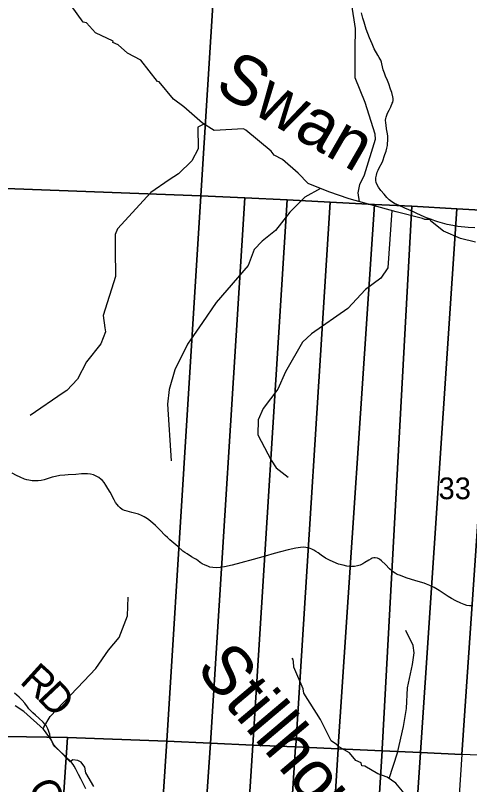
# Model space of a CAD drawing. Extents: x 0 to 34, y 0 to 22.
# Drawn here: x 6.766 to 7.641, y 15.074 to 16.555 of the extents above; entities that cross this region are included whole.
import ezdxf

# ---------------------------------------------------------------- set-up
doc = ezdxf.new("R2010")
doc.units = 0
for name, color, linetype in [('Default', 7, 'Continuous'), ('GM_X_County_Road', 7, 'Continuous'), ('GM_X_County_Road_Text', 7, 'Continuous'), ('GM_X_Minor_River', 7, 'Continuous'), ('GM_X_Minor_River_Text', 7, 'Continuous'), ('GM_X_Section', 7, 'Continuous'), ('GM_X_Section_Text', 7, 'Continuous'), ('GM_X_Township_Road', 7, 'Continuous')]:
    doc.layers.add(name, color=color, linetype=linetype)

msp = doc.modelspace()

# ---------------------------------------------------------------- linework, layer by layer
at = {"layer": 'Default'}
msp.add_lwpolyline([(7.6316, 14.1), (7.6406, 14.1), (7.7063, 15.1284), (7.6256, 15.132), (7.558, 14.1033)], close=True, dxfattribs=at)
at = {"layer": 'GM_X_County_Road'}
for points in [[(7.6442, 15.4183), (7.6401, 15.4183), (7.6354, 15.419), (7.6299, 15.4209), (7.6235, 15.4235), (7.6141, 15.4277), (7.6054, 15.4325), (7.599, 15.4363), (7.5818, 15.4477), (7.572, 15.4532), (7.5637, 15.4575), (7.5573, 15.46), (7.5528, 15.4616), (7.5461, 15.4637), (7.5354, 15.467), (7.5288, 15.4689), (7.5187, 15.4722), (7.5073, 15.4763), (7.5013, 15.4787), (7.497, 15.4811), (7.494, 15.483), (7.4908, 15.4855), (7.4862, 15.4896), (7.4784, 15.4978), (7.4711, 15.5047), (7.4669, 15.5078), (7.463, 15.5098), (7.4588, 15.5104), (7.4559, 15.5103), (7.4532, 15.5097), (7.4511, 15.5089), (7.4463, 15.5063), (7.439, 15.5016), (7.4347, 15.4991), (7.4297, 15.4966), (7.4246, 15.4949), (7.4188, 15.4937), (7.4143, 15.4938), (7.4095, 15.494), (7.4044, 15.4946), (7.3971, 15.4963), (7.3881, 15.4987), (7.3776, 15.5026), (7.3706, 15.5058), (7.3632, 15.5102), (7.3545, 15.5159), (7.3486, 15.5203), (7.3441, 15.5231), (7.3406, 15.5254), (7.337, 15.5273), (7.3337, 15.5287), (7.3293, 15.53), (7.3254, 15.5308), (7.3204, 15.5311), (7.315, 15.5307), (7.3058, 15.5291), (7.2914, 15.5259), (7.2761, 15.5221), (7.2641, 15.5191), (7.2468, 15.5141), (7.224, 15.5077), (7.1999, 15.5012), (7.1832, 15.4966), (7.1687, 15.4934), (7.1601, 15.4921), (7.154, 15.4916), (7.146, 15.492), (7.1404, 15.4929), (7.1362, 15.4943), (7.1311, 15.4964), (7.1256, 15.4993), (7.1219, 15.5016), (7.1173, 15.5052), (7.1133, 15.508), (7.111, 15.5094), (7.1051, 15.5127), (7.0967, 15.5181), (7.0922, 15.5208), (7.0882, 15.5236), (7.0783, 15.5325), (7.0634, 15.5453), (7.0585, 15.5498), (7.0545, 15.5536), (7.0442, 15.5644), (7.0355, 15.573), (7.026, 15.5813), (7.02, 15.5858), (7.0139, 15.5895), (7.0086, 15.5922), (7.0031, 15.5946), (6.9976, 15.5963), (6.9902, 15.5981), (6.9807, 15.6004), (6.9759, 15.6019), (6.9717, 15.604), (6.9678, 15.6068), (6.9643, 15.6099), (6.9616, 15.6131), (6.9587, 15.6171), (6.9559, 15.6222), (6.948, 15.6372), (6.9439, 15.6443), (6.9402, 15.6508), (6.9367, 15.6558), (6.9336, 15.6595), (6.9311, 15.6618), (6.9264, 15.6652), (6.9215, 15.6679), (6.916, 15.6703), (6.9101, 15.6717), (6.9046, 15.6725), (6.8984, 15.6726), (6.8929, 15.6721), (6.8822, 15.6712), (6.8676, 15.6702), (6.8607, 15.6698), (6.8514, 15.6689), (6.8429, 15.6674), (6.8364, 15.6657), (6.8209, 15.6608), (6.8155, 15.6595), (6.8093, 15.6587), (6.8042, 15.6586), (6.798, 15.6591), (6.7918, 15.6601), (6.788, 15.6609), (6.7834, 15.6622), (6.7752, 15.6657), (6.7676, 15.6692), (6.7592, 15.6739)], [(6.9012, 15.0659), (6.8919, 15.0851), (6.8875, 15.0934), (6.882, 15.1037), (6.8789, 15.1093), (6.8767, 15.1126), (6.8723, 15.1181), (6.8624, 15.1279), (6.8483, 15.1413), (6.8435, 15.146), (6.8397, 15.1507), (6.8372, 15.1548), (6.8357, 15.1579), (6.8343, 15.1613), (6.833, 15.1654), (6.8318, 15.1707), (6.8309, 15.1743), (6.8295, 15.1782), (6.8285, 15.1813), (6.8271, 15.1838), (6.8247, 15.1876), (6.8226, 15.1901), (6.8191, 15.1941), (6.811, 15.2015), (6.8044, 15.2074), (6.7995, 15.2121), (6.7955, 15.2157), (6.7919, 15.2196), (6.7888, 15.2235), (6.7836, 15.2305), (6.7786, 15.2364), (6.7729, 15.242), (6.7639, 15.2497)]]:
    msp.add_lwpolyline(points, dxfattribs=at)
at = {"layer": 'GM_X_Minor_River'}
for points in [[(7.1484, 16.3335), (7.1264, 16.3481), (7.09, 16.3792), (7.07, 16.394), (7.0424, 16.4277), (7.0393, 16.4281), (7.0076, 16.4691), (6.9815, 16.4827), (6.9637, 16.4986), (6.9535, 16.5032), (6.9542, 16.5058), (6.9198, 16.5221), (6.9024, 16.5414), (6.896, 16.5426), (6.8729, 16.5744), (6.8555, 16.5884), (6.8433, 16.5816), (6.8522, 16.5865)], [(7.4284, 16.1962), (7.426, 16.2136), (7.4292, 16.2298), (7.438, 16.2481), (7.4594, 16.3173), (7.4589, 16.3264), (7.4393, 16.3878), (7.4199, 16.4351), (7.4204, 16.4898), (7.4205, 16.5301), (7.414, 16.5758)], [(7.1302, 16.3465), (7.1169, 16.34), (7.1179, 16.2986), (7.1055, 16.2751), (7.0801, 16.2501), (7.0616, 16.2385), (7.0269, 16.2142), (6.9624, 16.1445), (6.9579, 16.1333), (6.9578, 16.1048), (6.9585, 16.0524), (6.935, 15.9772), (6.9381, 15.9535), (6.9394, 15.9459), (6.9304, 15.923), (6.9025, 15.8882), (6.8852, 15.8546), (6.8649, 15.8332), (6.8575, 15.8282), (6.7942, 15.785)], [(7.2052, 16.3367), (7.1484, 16.3335)], [(7.652, 16.1186), (7.6233, 16.1258), (7.5904, 16.1398), (7.565, 16.1598), (7.5658, 16.1621), (7.5545, 16.1625), (7.5499, 16.1644), (7.4989, 16.1772), (7.4089, 16.2021), (7.3696, 16.2153), (7.3298, 16.2319), (7.3105, 16.2516), (7.2799, 16.2778), (7.264, 16.2861), (7.2583, 16.2937), (7.2095, 16.3342), (7.2052, 16.3367)], [(7.3532, 16.2221), (7.3233, 16.2055), (7.2945, 16.1764), (7.267, 16.1408), (7.241, 16.1204), (7.2258, 16.1042), (7.2139, 16.0734), (7.1527, 16.0021), (7.1259, 15.9642), (7.0974, 15.9222), (7.0728, 15.8729), (7.0619, 15.8349), (7.0588, 15.8069), (7.0656, 15.6974)], [(7.4908, 16.1794), (7.4833, 16.0694), (7.4694, 16.0493), (7.44, 16.0275), (7.406, 15.991), (7.3361, 15.942), (7.319, 15.9258), (7.2859, 15.8688), (7.2709, 15.8354), (7.243, 15.7984), (7.2332, 15.7763), (7.2327, 15.7478), (7.2581, 15.6988), (7.2682, 15.684), (7.2911, 15.6658)], [(6.819, 15.1807), (6.8202, 15.1846), (6.833, 15.2047), (6.8978, 15.2733), (6.9208, 15.2972), (6.9449, 15.3329), (6.9653, 15.3569), (6.9817, 15.3989), (6.9828, 15.435)], [(7.4859, 15.0855), (7.5018, 15.1348), (7.5135, 15.186), (7.5191, 15.2204), (7.5211, 15.2602), (7.5307, 15.3051), (7.5341, 15.3277), (7.5319, 15.3415), (7.5176, 15.3708)], [(7.5633, 15.0001), (7.5423, 15.0098), (7.5298, 15.0295), (7.5279, 15.0318), (7.5116, 15.0614), (7.4987, 15.0766), (7.4817, 15.0883), (7.4636, 15.0947), (7.439, 15.1095), (7.4333, 15.1099), (7.4318, 15.1159), (7.4216, 15.1205), (7.4095, 15.1349), (7.3898, 15.1459), (7.3845, 15.1508), (7.3739, 15.158), (7.3535, 15.199), (7.3213, 15.2502), (7.3201, 15.2582), (7.302, 15.3), (7.3016, 15.3106), (7.3, 15.3167), (7.2982, 15.3155)], [(6.917, 15.0699), (6.9014, 15.0965), (6.8995, 15.1075), (6.8923, 15.117), (6.8859, 15.1204), (6.8761, 15.1215), (6.8715, 15.1177), (6.8507, 15.1386), (6.8398, 15.1484), (6.8352, 15.1594), (6.8197, 15.1807), (6.7819, 15.2148), (6.7652, 15.2254)]]:
    msp.add_lwpolyline(points, dxfattribs=at)
at = {"layer": 'GM_X_Section'}
for points in [[(7.1862, 17.219), (7.123, 16.2082), (6.0647, 16.248), (6.0651, 16.2532), (6.0768, 16.4347), (6.1041, 16.8596), (6.1312, 17.2799)], [(8.2333, 17.168), (8.2168, 16.9137), (8.2009, 16.6614), (8.1857, 16.4083), (8.1692, 16.1543), (8.0945, 16.1581), (8.0152, 16.1622), (7.938, 16.1663), (7.8569, 16.1703), (7.7763, 16.1745), (7.6973, 16.1784), (7.6162, 16.1827), (7.5294, 16.1877), (7.4574, 16.1913), (7.3717, 16.1957), (7.289, 16.1999), (7.2077, 16.2041), (7.123, 16.2082), (7.1862, 17.219)], [(6.0647, 16.248), (7.123, 16.2082), (7.0576, 15.1572), (6.8659, 15.1648), (6.6679, 15.168), (6.4645, 15.1779), (6.2754, 15.1876), (6.1131, 15.1956), (5.9993, 15.2017), (6.0505, 16.0207)], [(7.2077, 16.2041), (7.1412, 15.1536), (7.0576, 15.1572), (7.123, 16.2082)], [(7.289, 16.1999), (7.2228, 15.15), (7.1412, 15.1536), (7.2077, 16.2041)], [(7.3717, 16.1957), (7.3057, 15.1491), (7.3055, 15.1463), (7.2228, 15.15), (7.289, 16.1999)], [(7.4574, 16.1913), (7.3875, 15.1469), (7.3872, 15.1426), (7.3055, 15.1463), (7.3057, 15.1491), (7.3717, 16.1957)], [(7.5294, 16.1877), (7.4722, 15.1421), (7.472, 15.1389), (7.3872, 15.1426), (7.3875, 15.1469), (7.4574, 16.1913)], [(7.6162, 16.1827), (7.5463, 15.1356), (7.472, 15.1389), (7.4722, 15.1421), (7.5294, 16.1877)], [(7.6973, 16.1784), (7.6256, 15.132), (7.5463, 15.1356), (7.6162, 16.1827)], [(7.7763, 16.1745), (7.7089, 15.1283), (7.7063, 15.1284), (7.6256, 15.132), (7.6973, 16.1784)], [(6.6679, 15.168), (6.8659, 15.1648), (6.8091, 14.313), (6.7968, 14.3133), (6.7574, 14.3154), (6.7525, 14.3161), (6.7499, 14.3155), (6.742, 14.3162), (6.7242, 14.3154), (6.7094, 14.3154), (6.7014, 14.3158), (6.6848, 14.315), (6.6749, 14.3142), (6.656, 14.3134), (6.6393, 14.313), (6.6211, 14.3149), (6.6082, 14.3162)], [(6.8659, 15.1648), (7.0576, 15.1572), (6.9982, 14.2655), (6.9883, 14.2685), (6.9712, 14.273), (6.9538, 14.2778), (6.9424, 14.2808), (6.9219, 14.2883), (6.9136, 14.2913), (6.9083, 14.2928), (6.9034, 14.2932), (6.8992, 14.2947), (6.8855, 14.2988), (6.8722, 14.3022), (6.8635, 14.3044), (6.851, 14.307), (6.8351, 14.3107), (6.8249, 14.3118), (6.8091, 14.313)], [(7.1412, 15.1536), (7.0789, 14.2451), (7.0683, 14.2494), (7.0524, 14.2558), (7.0459, 14.2584), (7.0399, 14.2607), (7.03, 14.2633), (7.022, 14.2656), (7.0175, 14.2652), (7.0126, 14.2633), (7.0088, 14.2621), (7.0042, 14.2625), (7.0016, 14.2632), (6.9982, 14.2655), (7.0576, 15.1572)], [(7.2228, 15.15), (7.1628, 14.2135), (7.1438, 14.2213), (7.1275, 14.2273), (7.1104, 14.2337), (7.1051, 14.237), (7.1006, 14.2408), (7.0964, 14.2427), (7.0918, 14.2431), (7.0854, 14.2434), (7.0812, 14.2442), (7.0789, 14.2451), (7.1412, 15.1536)], [(7.3055, 15.1463), (7.2438, 14.1829), (7.2394, 14.1849), (7.2288, 14.189), (7.2102, 14.1961), (7.2011, 14.1991), (7.184, 14.2047), (7.1666, 14.2119), (7.1628, 14.2135), (7.2228, 15.15)], [(7.3872, 15.1426), (7.3259, 14.1534), (7.3203, 14.1537), (7.3119, 14.1548), (7.3024, 14.1574), (7.2903, 14.1615), (7.2751, 14.1675), (7.2679, 14.1709), (7.252, 14.1792), (7.2438, 14.1829), (7.3055, 15.1463)], [(7.472, 15.1389), (7.4083, 14.1246), (7.4029, 14.1267), (7.3851, 14.1331), (7.3771, 14.1357), (7.3692, 14.1376), (7.3635, 14.1394), (7.3559, 14.1406), (7.351, 14.1424), (7.3468, 14.1447), (7.3449, 14.1466), (7.3441, 14.1492), (7.3441, 14.156), (7.3437, 14.1579), (7.343, 14.1587), (7.3418, 14.1591), (7.3407, 14.1591), (7.3358, 14.1568), (7.3305, 14.1541), (7.3259, 14.1534), (7.3872, 15.1426)], [(7.5463, 15.1356), (7.477, 14.1069), (7.4448, 14.1083), (7.4337, 14.1143), (7.4219, 14.1192), (7.4083, 14.1246), (7.472, 15.1389)], [(7.6256, 15.132), (7.558, 14.1033), (7.477, 14.1069), (7.5463, 15.1356)]]:
    msp.add_lwpolyline(points, close=True, dxfattribs=at)
at = {"layer": 'GM_X_Township_Road'}
msp.add_lwpolyline([(7.6505, 16.1463), (7.6377, 16.1471), (7.618, 16.1488), (7.608, 16.1505), (7.5971, 16.1529), (7.5792, 16.1579), (7.5733, 16.1598), (7.567, 16.162), (7.5576, 16.1658), (7.5476, 16.1702), (7.5375, 16.1748), (7.5312, 16.1776), (7.5161, 16.1839), (7.5046, 16.189), (7.4962, 16.1934), (7.4906, 16.1965), (7.4858, 16.2003), (7.4812, 16.2047), (7.4759, 16.2108), (7.4696, 16.2184), (7.4653, 16.2247), (7.4621, 16.2301), (7.4607, 16.2335), (7.4601, 16.2375), (7.46, 16.2426), (7.461, 16.2478), (7.4626, 16.2535), (7.4643, 16.2571), (7.4659, 16.2604), (7.4725, 16.2735), (7.4776, 16.2872), (7.4797, 16.2938), (7.4811, 16.2999), (7.4823, 16.305), (7.4827, 16.308), (7.483, 16.3148), (7.483, 16.3228), (7.4824, 16.3275), (7.4807, 16.3371), (7.4796, 16.3443), (7.4792, 16.3483), (7.4789, 16.3536), (7.4794, 16.3569), (7.4798, 16.3596), (7.4811, 16.3632), (7.4826, 16.3671), (7.4855, 16.3731), (7.4886, 16.3793), (7.4917, 16.3862), (7.4924, 16.3885), (7.4932, 16.3914), (7.4935, 16.3952), (7.4929, 16.3983), (7.4905, 16.4069), (7.4884, 16.4134), (7.4847, 16.4238), (7.4823, 16.4303), (7.4788, 16.4385), (7.4765, 16.4442), (7.4751, 16.4476), (7.4743, 16.4506), (7.4718, 16.4621), (7.4707, 16.4656), (7.4694, 16.4691), (7.4684, 16.4714), (7.4663, 16.4746), (7.4636, 16.4791), (7.457, 16.4912), (7.4526, 16.5004), (7.448, 16.512), (7.4416, 16.5288), (7.4372, 16.5421), (7.435, 16.5498), (7.4335, 16.5554), (7.4324, 16.5605)], dxfattribs=at)

# ---------------------------------------------------------------- texts
at = {"layer": 'GM_X_County_Road_Text'}
for s, rotation, p in [('R', 317.7996, (6.7721, 15.2704)), ('D', 313.3796, (6.8059, 15.2398)), ('C', 297.5557, (6.7876, 15.0682))]:
    msp.add_text(s, height=0.0568, rotation=rotation, dxfattribs=at).set_placement(p)
at = {"layer": 'GM_X_Minor_River_Text'}
for s, height, rotation, p in [('Swan', 0.0947, 329.9982, (7.1465, 16.4107)), ('Stillhouse', 0.09469, 310.1347, (7.1113, 15.2962))]:
    msp.add_text(s, height=height, rotation=rotation, dxfattribs=at).set_placement(p)
at = {"layer": 'GM_X_Section_Text'}
msp.add_text('33', height=0.04186, rotation=0, dxfattribs=at).set_placement((7.5808, 15.6235))

doc.saveas('drawing.dxf')
